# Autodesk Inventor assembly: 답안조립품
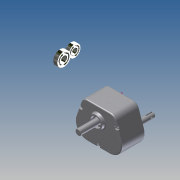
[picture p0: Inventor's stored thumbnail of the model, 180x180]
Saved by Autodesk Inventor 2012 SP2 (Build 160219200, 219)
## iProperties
Created: 2014-12
Part Number: 답안조립품
Document SubType Name: Assembly
Designer: cad-02
Author: cad-02
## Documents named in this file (9)
- C:\Users\cad-02\Desktop\441209V1021\답안조립품.iam
- C:\Users\cad-02\Desktop\441209V1021\본체.ipt
- C:\Users\cad-02\Desktop\441209V1021\커버.ipt
- C:\Users\cad-02\Desktop\441209V1021\메인축.ipt
- C:\Users\cad-02\Desktop\441209V1021\서브축.ipt
- C:\Users\cad-02\Desktop\441209V1021\베어링- 6202.ipt
- C:\Users\cad-02\Desktop\441209V1021\서브기어.ipt
- C:\Users\cad-02\Desktop\441209V1021\베어링- 6203.ipt
- C:\Users\cad-02\Desktop\441209V1021\오일시일-D-15.ipt
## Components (8 placed, 3 different names)
1. KS B 2023 6202 - 15 x 35 x 11:1
2. KS B 2023 6202 - 15 x 35 x 11:2
3. KS B 2023 6203 - 17 x 40 x 12:1
4. KS B 2023 6203 - 17 x 40 x 12:2
5. KS B 2023 6203 - 17 x 40 x 12:3
6. KS B 2023 6203 - 17 x 40 x 12:4
7. KS B 2804 D D - 15 30 7:1
8. KS B 2804 D D - 15 30 7:2
